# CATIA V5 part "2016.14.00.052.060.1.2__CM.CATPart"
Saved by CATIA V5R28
Part number: 2016.14.00.052.060.1.2__CM
Property "id_number": "2016.14.00.052.060.1.2"
Publications: "Absolute Axis System", "driver", "slider", "base", "cam diagram"
Bounding box of the stored display mesh (mm): x -60 to 180, y -49 to 49, z 0 to 200
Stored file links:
  N:\B2\Normteile\K\2016\11-14\005\cm\2016.14.00.052.060.1.2__CM.CATPart
  H:\CAD_Startmodelle\Tests\fill-in_PRT-SL_TEMPLATE.xlsx
  H:\CAD_Startmodelle\V5-R24\R24_TEMPLATE_PRT_FIBRO_CAM_TECNOLOGIES_INDEX.xlsx
  H:\z_Einordnen\170511__Anfrage_TK_HN\170511__CC01_TKHN.CATPart
  N:\B2\Normteile\K\2016\9xxx\2016.9024.1705.001\Entwurf_\170511__CC01_TKHN.CATPart
  N:\B2\Normteile\K\2016\9xxx\2016.9024.1707.006\Konstruktion\2016.9024.1707.006__HP__CUSTOMIZED_CAM_CM.CATPart
  N:\B2\Normteile\K\2016\9xxx\2016.9024.1707.005\Konstruktion\2016.9024.1707.005__HP__CUSTOMIZED_CAM_CM.CATPart
  N:\B2\Normteile\K\2016\9xxx\2016.9024.1707.008\Konstruktion\2016.9024.1707.008__HP__CUSTOMIZED_CAM_CM.CATPart
  N:\B2\Normteile\K\2016\9xxx\2016.9024.1707.009\Konstruktion\2016.9024.1707.009__HP__CUSTOMIZED_CAM_CM.CATPart
  N:\B2\Normteile\K\2016\9xxx\2016.9024.1707.010\Konstruktion\2016.9024.1707.010__HP__CUSTOMIZED_CAM_CM.CATPart
  N:\B2\Normteile\K\2016\9xxx\2016.9024.1708.002\Konstruktion\2016.9024.1708.002__HP__CUSTOMIZED_CAM_CM.CATPart
  N:\B2\Normteile\K\2016\9xxx\2016.9024.1802.001\Konstruktion\2016.9024.1802.001__HP__CUSTOMIZED_CAM_CM.CATPart
  N:\B2\Normteile\K\2016\9xxx\2016.9024.1802.002\Konstruktion\2016.9024.1802.002__HP__CUSTOMIZED_CAM_CM.CATPart
  N:\B2\Normteile\K\2016\9xxx\2016.9024.1811.003\Konstruktion\2016.9024.1811.003__HP__CUSTOMIZED_CAM_CM.CATPart
  N:\B2\Normteile\K\2016\9xxx\2016.9015.1811.001\Konstruktion\am\2016.9015.1811.001__AM__FCC_HV_DMC_0125-00.CATPart
  N:\B2\Normteile\K\2016\9xxx\2016.9024.1811.009\Konstruktion\2016.9024.1811.009__HP__CUSTOMIZED_CAM_CM.CATPart
  N:\B2\Normteile\K\2016\9xxx\2016.9024.1911.002\Konstruktion\am\2016.9024.1911.002__AM__CUSTOMIZED_CAM_CM.CATPart
  N:\B2\Normteile\K\2016\9xxx\2016.9024.2002.006\Konstruktion\2016.9024.2002.006__AM.CATPart
  N:\B2\Normteile\K\2016\9xxx\2016.9024.2004.001\Konstruktion\2016.9024.2004.001__AM__FCC_HV_CAEC_0260-45.CATPart
  N:\B2\Normteile\K\2016\9xxx\2016.9024.2006.002\Konstruktion\2016.9024.2006.002__AM__FCC_HV_CAEC_0260-40.CATPart
  N:\B2\Normteile\K\2016\9xxx\2016.9024.2006.005\Konstruktion\am\2016.9024.2006.005__AM__CFCC_HV_AEPC_0080-65.CATPart
  N:\B2\Normteile\K\2016\9xxx\2016.9024.2006.004\Konstruktion\am\2016.9024.2006.004__AM__CFCC_HV_AEC_0210-35.CATPart
  N:\B2\Normteile\K\2016\9xxx\2016.9026.2006.001\Konstruktion\am\2016.9026.2006.001__AM__FCC_LV_CAEC_0180-40.CATPart
  N:\B2\Normteile\K\2016\9xxx\2016.9015.2007.001\Konstruktion\am\2016.9015.2007.001__AM__FCC_HV_CDMPC_0090-00.CATPart
  N:\B2\Normteile\K\2016\9xxx\2016.9024.2005.001\Konstruktion\am\2016.9024.2005.001__AM__CFCC_HV_AEPC_1400-70.CATPart
  N:\B2\Normteile\K\2016\9xxx\2016.9024.2007.004\Konstruktion\am\2016.9024.2007.004__AM__CFCC_HV_AEC_1250-80.CATPart
  N:\B2\Normteile\K\2016\11-14\005\2016.11.00.052.040.1.02__AS__DIE_MOUNT_CAM__W52_A0_S40.CATProduct
  N:\B2\Normteile\K\2016\11-14\005\cm\2016.11.00.052.025.1.2__CM.CATPart
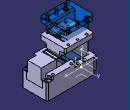
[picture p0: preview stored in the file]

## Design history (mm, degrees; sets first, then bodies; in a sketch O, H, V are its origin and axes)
Parameters
  group "process_parameters"
    modeltype = ""
    stocklist = ""
    id_number = "2016.14.00.052.060.1.2"
    id_number_rough_part = ""
    revision_index = ""
    revision_date = ""
    revision_description = ""
    category = ""
    material = ""
    manufacturing_information = ""
    standard = ""
  group "release_parameters_startmodel"
    sm_revision_index = "2016_00" {design table}
    sm_revision_date = "20.08.2016" {design table}
    sm_revision_name = "Meyer" {design table}
    sm_revision_description = "new part template FIBRO cam tecnologies" {design table}
AxisSystem1: origin (0, 0, 0), X (1, 0, 0), Y (0, 1, 0), Z (0, 0, 1)
Set1 "reference elements"
  Sketch1 "cam diagram" on ZX plane of AxisSystem1, origin (0, 0, 0), H (-1, 0, 0), V (0, 0, 1)
    line L1 (0, 0) -> (60, 0)
    line L2 (60, 0) -> (0, 60)
    point P2 (0, 60)
    line L3 (0, 60) -> (0, 0)
    length L1 = 60
    angle H L2 = 45
    horizontal: L1 H
    coincidence: P2 V
    vertical: L3 V
Body1 "finished_part" (main body)
  Body2 "rough_part"
  Add1 "rough_part": tool Body2
  Body3 "milling operations"
  Remove1 "milling operations": tool Body3
  Body4 "drilling operations"
  Remove2 "drilling operations": tool Body4
Body5 "driver"
  Solid1: solid without history
Body6 "slider"
  Solid2: solid without history
Body7 "base"
  Solid3: solid without history
Body8 "opened position"
  Body9 "slider"
    Body10 "slider"
      Solid4: linked copy from another document
    Assemble1: tool Body10
    Translate1: FirstPoint vertex [element of Sketch1 | element of Sketch1], SecondPoint vertex [element of Sketch1 | element of Sketch1], ToTransfor Assemble1
  Assemble2: tool Body9
  Body11 "driver"
    Body12 "driver"
      Solid5: linked copy from another document
    Assemble3: tool Body12
    Translate2: FirstPoint vertex [element of Sketch1 | element of Sketch1], SecondPoint vertex [element of Sketch1 | element of Sketch1], ToTransfor Assemble3
  Assemble4: tool Body11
